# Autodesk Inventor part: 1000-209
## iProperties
Created: 2007-03
Part Number: 1000-209
Document SubType Name: Modeling
Designer: Andy Moles
Material: ABS Plastic
Mass: 22.2211 g
Surface Area: 136.352 cm^2
Volume: 20.9633 cm^3
Density: 1.06 g/cm^3
Author: Andy Moles
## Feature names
1. Base1
2. Extrusion1
